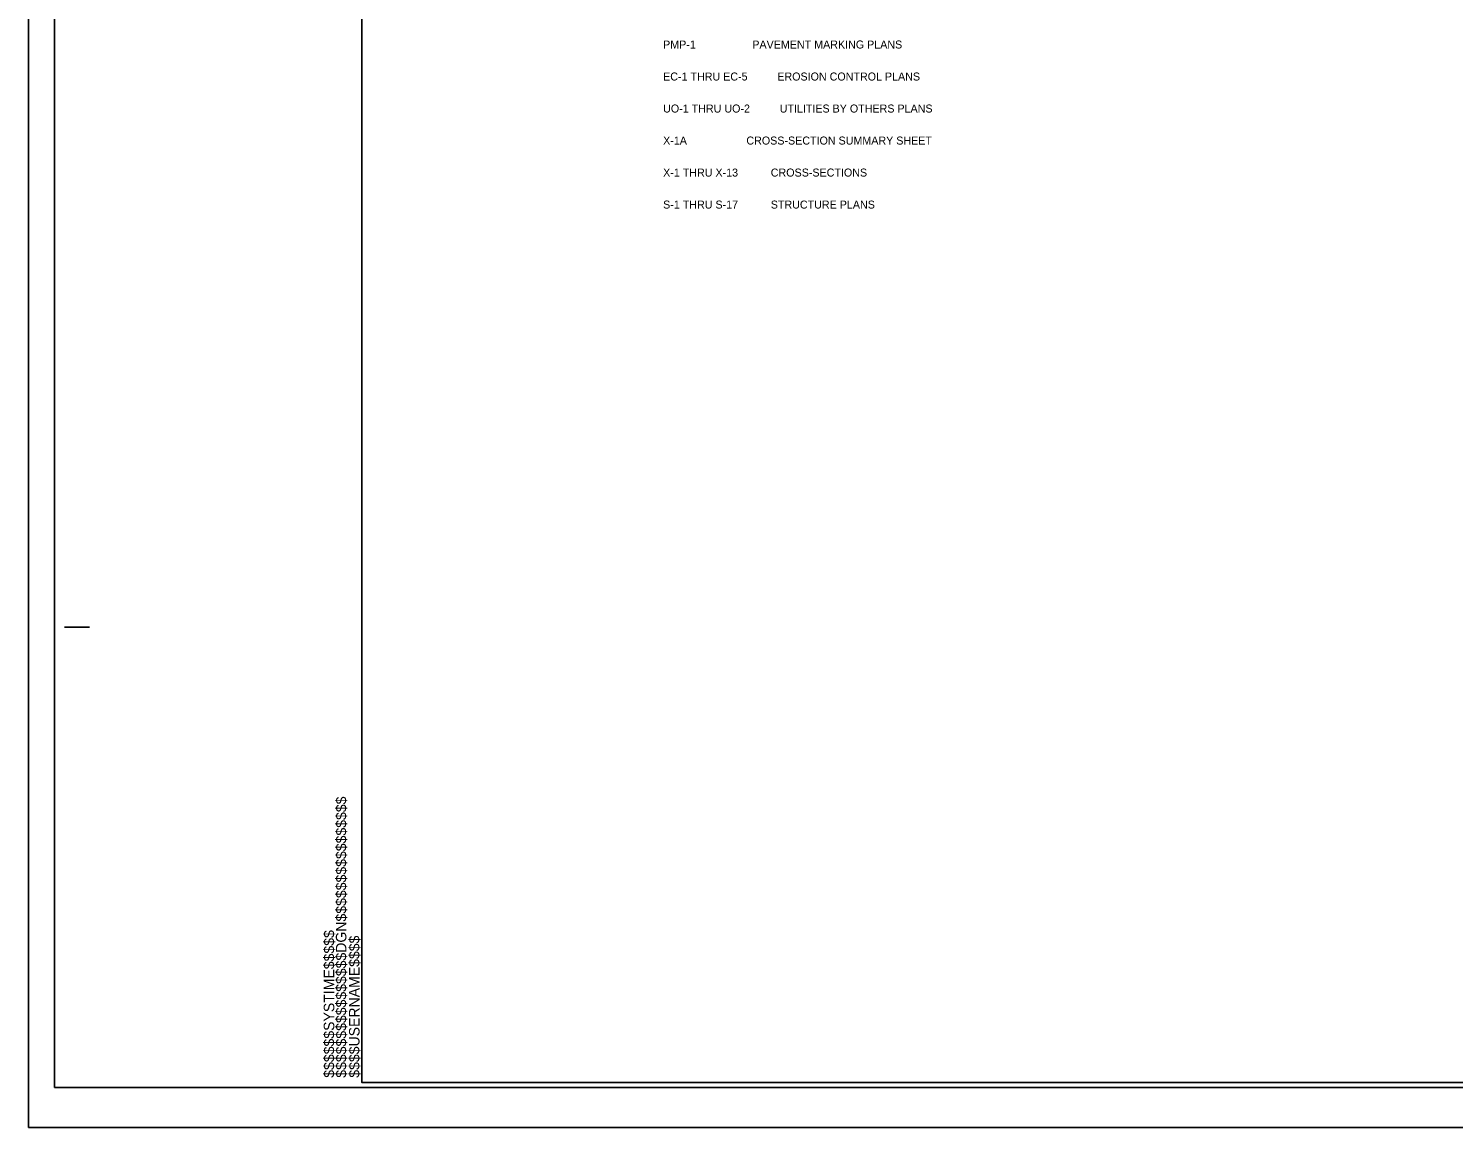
# Model space of a CAD drawing. Extents: x 573606 to 575290, y -53273 to -52178.
# Drawn here: x 573606 to 574319, y -53273 to -52723 of the extents above; entities that cross this region are included whole.
import ezdxf

# ---------------------------------------------------------------- set-up
doc = ezdxf.new("R2010")
doc.units = 0
for name, color, linetype in [('Sheet Cutting Line CELL', 7, 'Continuous'), ('Sheet Data Text CELL', 7, 'Continuous'), ('Sheet Plan CELL', 7, 'Continuous'), ('Sheet Plot Border Inside CELL', 7, 'Continuous'), ('Sheet Plot Border Outside CELL', 7, 'Continuous')]:
    doc.layers.add(name, color=color, linetype=linetype)

msp = doc.modelspace()

# ---------------------------------------------------------------- linework, layer by layer
at = {"layer": 'Sheet Cutting Line CELL'}
for p, q in [((573606.46, -52177.62), (573606.46, -53272.62)), ((573606.46, -53272.62), (575289.96, -53272.62))]:
    msp.add_line(p, q, dxfattribs=at)
at = {"layer": 'Sheet Plan CELL'}
for p, q in [((573624.46, -53022.62), (573636.96, -53022.62)), ((573772.96, -53250.12), (573772.96, -53250.12))]:
    msp.add_line(p, q, dxfattribs=at)
msp.add_lwpolyline([(575272.96, -52200.12), (573772.96, -52200.12), (573772.96, -53250.12), (575272.96, -53250.12)], close=True, dxfattribs=at)
at = {"layer": 'Sheet Plot Border Inside CELL'}
msp.add_lwpolyline([(573619.46, -53252.62), (575285.46, -53252.62), (575285.46, -52197.62), (573619.46, -52197.62)], close=True, dxfattribs=at)
at = {"layer": 'Sheet Plot Border Outside CELL'}
msp.add_lwpolyline([(573606.46, -53272.62), (575289.96, -53272.62), (575289.96, -52177.62), (573606.46, -52177.62)], close=True, dxfattribs=at)

# ---------------------------------------------------------------- texts
at = {"layer": 'Sheet Data Text CELL'}
for s, p in [('PMP-1                   PAVEMENT MARKING PLANS', (573923.59, -52733.36)), ('EC-1 THRU EC-5          EROSION CONTROL PLANS', (573923.59, -52749.36)), ('UO-1 THRU UO-2          UTILITIES BY OTHERS PLANS', (573923.59, -52765.36)), ('X-1A                    CROSS-SECTION SUMMARY SHEET', (573923.59, -52781.36)), ('X-1 THRU X-13           CROSS-SECTIONS', (573923.59, -52797.36)), ('S-1 THRU S-17           STRUCTURE PLANS', (573923.59, -52813.36))]:
    msp.add_text(s, height=4, dxfattribs=at).set_placement(p)
at = {"layer": 'Sheet Plan CELL'}
for s, p in [('$$$$$$$$$$$$$$$$DGN$$$$$$$$$$$$$$$$', (573765.31, -53247.76)), ('$$$$$$SYSTIME$$$$$', (573759.26, -53247.76)), ('$$$$USERNAME$$$$', (573771.88, -53247.75))]:
    msp.add_text(s, height=5.25, rotation=90, dxfattribs=at).set_placement(p)

doc.saveas('drawing.dxf')
